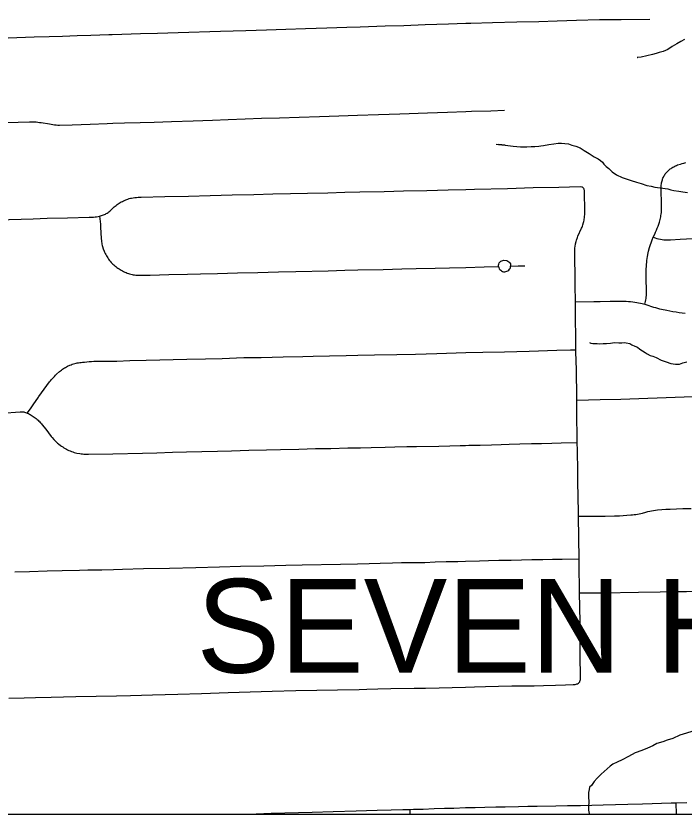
# Model space of a CAD drawing. Extents: x -59 to 82, y -3 to 49.
# Drawn here: x -13.455 to -12.781, y 28.548 to 29.355 of the extents above; entities that cross this region are included whole.
import ezdxf

# ---------------------------------------------------------------- set-up
doc = ezdxf.new("R2010")
doc.units = 0
for name, color, linetype in [('GM_X_City_Street', 7, 'Continuous'), ('GM_X_Corporation', 7, 'Continuous'), ('GM_X_Corporation_Text', 7, 'Continuous'), ('GM_X_County_Road', 7, 'Continuous'), ('GM_X_Minor_River', 7, 'Continuous'), ('SH_Data', 7, 'Continuous')]:
    doc.layers.add(name, color=color, linetype=linetype)

msp = doc.modelspace()

# ---------------------------------------------------------------- linework, layer by layer
at = {"layer": 'GM_X_City_Street'}
for p, q in [((-12.78827, 28.54818), (-12.78831, 28.55954)), ((-13.05725, 28.54818), (-13.05736, 28.55288))]:
    msp.add_line(p, q, dxfattribs=at)
for points in [[(-13.46337, 29.33276), (-13.43718, 29.33366), (-13.42205, 29.33413), (-13.40839, 29.33448), (-13.39371, 29.33497), (-13.37997, 29.33543), (-13.3617, 29.33599), (-13.3582, 29.33609), (-13.34859, 29.33639), (-13.3295, 29.33704), (-13.31241, 29.33749), (-13.29147, 29.33808), (-13.24877, 29.33943), (-13.22319, 29.34018), (-13.20232, 29.34083), (-13.18265, 29.34143), (-13.16294, 29.34206), (-13.1413, 29.34275), (-13.12105, 29.34341), (-13.10769, 29.34386), (-13.08234, 29.34487), (-13.0637, 29.3453), (-13.0422, 29.34605), (-13.01855, 29.34677), (-13.001, 29.34743), (-12.99602, 29.34762), (-12.97416, 29.34817), (-12.94934, 29.34878), (-12.92711, 29.34937), (-12.90856, 29.34997), (-12.88922, 29.35043), (-12.86577, 29.35111), (-12.84394, 29.3513), (-12.81496, 29.35171)], [(-13.47479, 29.2468), (-13.45325, 29.24762), (-13.44195, 29.2479), (-13.43686, 29.24779), (-13.43517, 29.24767), (-13.43348, 29.24751), (-13.43179, 29.24731), (-13.43011, 29.24707), (-13.4216, 29.2457), (-13.41991, 29.24539), (-13.41822, 29.24512), (-13.41651, 29.2449), (-13.4148, 29.24472), (-13.41309, 29.24458), (-13.41136, 29.2445), (-13.3986, 29.24485), (-13.38066, 29.24539), (-13.36336, 29.24601), (-13.35762, 29.24633), (-13.34584, 29.24669), (-13.33, 29.2472), (-13.31575, 29.24755), (-13.29843, 29.24815), (-13.27656, 29.24897), (-13.25699, 29.24964), (-13.24095, 29.25011), (-13.22386, 29.25078), (-13.20728, 29.25138), (-13.18928, 29.25182), (-13.16932, 29.25261), (-13.14871, 29.25321), (-13.12932, 29.25387), (-13.11049, 29.25444), (-13.0891, 29.25519), (-13.0678, 29.25592), (-13.0398, 29.25691), (-13.01944, 29.25761), (-13.00103, 29.2583), (-12.99533, 29.25852), (-12.97585, 29.25911), (-12.96186, 29.2596)], [(-12.81999, 29.06337), (-12.81964, 29.06483), (-12.81933, 29.06631), (-12.81907, 29.06779), (-12.81885, 29.06927), (-12.81868, 29.07077), (-12.81857, 29.07227), (-12.81849, 29.07376), (-12.81878, 29.09285), (-12.81868, 29.0994), (-12.81857, 29.10158), (-12.8184, 29.10376), (-12.8182, 29.10593), (-12.81798, 29.10781), (-12.81772, 29.1097), (-12.81742, 29.11158), (-12.81671, 29.11531), (-12.8163, 29.11717), (-12.81537, 29.12085), (-12.81484, 29.12268), (-12.81341, 29.12662), (-12.81264, 29.12858), (-12.81159, 29.13112), (-12.81015, 29.13435), (-12.80925, 29.13625), (-12.80839, 29.13822), (-12.80757, 29.14021), (-12.80678, 29.14221), (-12.80604, 29.14423), (-12.80535, 29.14626), (-12.80496, 29.14764), (-12.8046, 29.14902), (-12.80429, 29.15042), (-12.80401, 29.15183), (-12.80377, 29.15324), (-12.80358, 29.15466), (-12.80342, 29.15608), (-12.8033, 29.15751), (-12.80323, 29.15894), (-12.80335, 29.17038), (-12.80347, 29.17372), (-12.80362, 29.17705), (-12.8037, 29.17819), (-12.80364, 29.18275), (-12.80352, 29.18388), (-12.80337, 29.185), (-12.80317, 29.18613), (-12.80294, 29.18724), (-12.80266, 29.18835), (-12.80241, 29.18925), (-12.80211, 29.19015), (-12.80177, 29.19103), (-12.80139, 29.19189), (-12.80097, 29.19273), (-12.80051, 29.19356), (-12.80002, 29.19436), (-12.79948, 29.19514), (-12.79892, 29.19588), (-12.79831, 29.19661), (-12.79767, 29.1973), (-12.79692, 29.19806), (-12.79614, 29.1988), (-12.79533, 29.19949), (-12.79449, 29.20016), (-12.79363, 29.20079), (-12.79274, 29.20139), (-12.79183, 29.20195), (-12.7909, 29.20248), (-12.78994, 29.20296), (-12.78898, 29.20342), (-12.78799, 29.20383), (-12.78699, 29.2042), (-12.7842, 29.20513), (-12.78241, 29.20569), (-12.78061, 29.2062), (-12.7788, 29.20668)], [(-13.47484, 29.14867), (-13.43808, 29.14988), (-13.4241, 29.15033), (-13.40347, 29.15088), (-13.38163, 29.15139), (-13.37702, 29.15157), (-13.37547, 29.15168), (-13.37397, 29.15186), (-13.37243, 29.15209), (-13.37121, 29.15235), (-13.36991, 29.15268), (-13.36892, 29.15299), (-13.36794, 29.15334), (-13.36697, 29.15373), (-13.36603, 29.15416), (-13.3651, 29.15462), (-13.36419, 29.15513), (-13.3633, 29.15567), (-13.36244, 29.15624), (-13.3616, 29.15685), (-13.36078, 29.1575), (-13.35918, 29.159), (-13.35711, 29.16099), (-13.35619, 29.16182), (-13.35525, 29.16263), (-13.35429, 29.16341), (-13.35329, 29.16415), (-13.35228, 29.16488), (-13.35124, 29.16556), (-13.35018, 29.16621), (-13.3491, 29.16683), (-13.348, 29.16741), (-13.34689, 29.16796), (-13.34576, 29.16847), (-13.34462, 29.16896), (-13.34346, 29.1694), (-13.34228, 29.1698), (-13.34109, 29.17018), (-13.3399, 29.17051), (-13.33869, 29.1708), (-13.33706, 29.17108), (-13.33541, 29.17131), (-13.33377, 29.17149), (-13.33212, 29.17164), (-13.33046, 29.17175), (-13.32881, 29.17182), (-13.30501, 29.17227), (-13.28101, 29.17279), (-13.25938, 29.17341), (-13.23708, 29.17391), (-13.21507, 29.17447), (-13.19597, 29.17494), (-13.17815, 29.17538), (-13.16084, 29.17582), (-13.14031, 29.17618), (-13.12304, 29.17659), (-13.10809, 29.17698), (-13.08351, 29.17756), (-13.06378, 29.17805), (-13.04026, 29.17857), (-13.01888, 29.17909), (-13.00106, 29.17945), (-12.99228, 29.17963), (-12.95873, 29.18054), (-12.93303, 29.18138), (-12.90692, 29.18188), (-12.88549, 29.18243), (-12.8839, 29.18222), (-12.88352, 29.18207), (-12.88317, 29.18189), (-12.88277, 29.1816), (-12.88231, 29.18114), (-12.88176, 29.18048)], [(-12.88525, 28.68413), (-12.88542, 28.71065), (-12.88555, 28.74249), (-12.88601, 28.77166), (-12.88618, 28.78226), (-12.88636, 28.79084), (-12.88651, 28.80019), (-12.88659, 28.80601), (-12.88671, 28.8275), (-12.88697, 28.84914), (-12.88707, 28.85287), (-12.88773, 28.88413), (-12.88789, 28.89468), (-12.88825, 28.91566), (-12.88833, 28.92362), (-12.88877, 28.95595), (-12.88877, 28.9665), (-12.88885, 28.97722), (-12.88911, 28.98909), (-12.88923, 28.99934), (-12.8894, 29.00421), (-12.88972, 29.0175), (-12.88992, 29.02548), (-12.89007, 29.05393), (-12.89009, 29.06598), (-12.89056, 29.08272), (-12.89065, 29.08966), (-12.89092, 29.11234), (-12.89069, 29.1204), (-12.89052, 29.12173), (-12.89006, 29.12439), (-12.88945, 29.12701), (-12.88909, 29.1283), (-12.88826, 29.13086), (-12.88779, 29.13212), (-12.88403, 29.14023), (-12.88355, 29.14135), (-12.88312, 29.14249), (-12.88272, 29.14364), (-12.88203, 29.14599), (-12.88175, 29.14717), (-12.8815, 29.14837), (-12.8813, 29.14957), (-12.88113, 29.15078), (-12.88101, 29.15199), (-12.88088, 29.15433), (-12.8808, 29.15667), (-12.88122, 29.17818), (-12.88143, 29.17984), (-12.88176, 29.18048)], [(-13.37121, 29.15235), (-13.37083, 29.14965), (-13.3705, 29.14694), (-13.37021, 29.14423), (-13.36996, 29.14151), (-13.36936, 29.12988), (-13.3692, 29.12755), (-13.36906, 29.12639), (-13.36888, 29.12524), (-13.36866, 29.12409), (-13.3684, 29.12296), (-13.36811, 29.12183), (-13.36741, 29.11961), (-13.36651, 29.11727), (-13.36597, 29.11604), (-13.3654, 29.11483), (-13.36479, 29.11364), (-13.36413, 29.11247), (-13.36344, 29.11132), (-13.36271, 29.1102), (-13.36195, 29.1091), (-13.36114, 29.10803), (-13.3603, 29.10698), (-13.35923, 29.10581), (-13.3577, 29.10411), (-13.35671, 29.1032), (-13.35569, 29.10232), (-13.35465, 29.10148), (-13.35358, 29.10066), (-13.35248, 29.09989), (-13.35137, 29.09914), (-13.35023, 29.09843), (-13.34907, 29.09775), (-13.34789, 29.09711), (-13.34669, 29.0965), (-13.34547, 29.09593), (-13.34424, 29.09539), (-13.34306, 29.09496), (-13.34187, 29.09455), (-13.34067, 29.09419), (-13.33945, 29.09387), (-13.33822, 29.09359), (-13.33699, 29.09334), (-13.33575, 29.09313), (-13.3345, 29.09297), (-13.33325, 29.09284), (-13.332, 29.09276), (-13.31984, 29.09295), (-13.30107, 29.09345), (-13.28226, 29.09393), (-13.2691, 29.09418), (-13.25195, 29.09462), (-13.23169, 29.09506), (-13.21127, 29.09565), (-13.19028, 29.09618), (-13.17267, 29.09659), (-13.13993, 29.09738), (-13.12329, 29.09776), (-13.1101, 29.09812), (-13.08461, 29.09866), (-13.0656, 29.09915), (-13.05098, 29.09943), (-13.03206, 29.09986), (-13.01744, 29.10024), (-13.00108, 29.10074), (-12.98234, 29.1013), (-12.96801, 29.10171)], [(-12.81159, 29.13112), (-12.80982, 29.13058), (-12.80803, 29.13007), (-12.80624, 29.12962), (-12.80444, 29.12921), (-12.80266, 29.12877), (-12.80079, 29.12854), (-12.79799, 29.12847), (-12.79426, 29.12857), (-12.78424, 29.12919), (-12.77156, 29.12999)], [(-12.96801, 29.10171), (-12.96788, 29.10304), (-12.96768, 29.10411), (-12.96728, 29.10517), (-12.96631, 29.1062), (-12.96548, 29.10683), (-12.96456, 29.10733), (-12.96359, 29.10769), (-12.96256, 29.1079), (-12.95947, 29.10762), (-12.95838, 29.10706), (-12.9574, 29.10632), (-12.95654, 29.10545), (-12.95594, 29.1043), (-12.95574, 29.10324), (-12.95567, 29.10205)], [(-12.96801, 29.10171), (-12.96775, 29.10045), (-12.96722, 29.09926), (-12.96655, 29.09853), (-12.96567, 29.09774), (-12.96489, 29.09713), (-12.96401, 29.09667), (-12.96306, 29.09638), (-12.96171, 29.09627), (-12.96048, 29.09645), (-12.95943, 29.0968), (-12.95844, 29.09731), (-12.95755, 29.09797), (-12.95678, 29.09876), (-12.95607, 29.09972), (-12.9558, 29.10059), (-12.95567, 29.10205)], [(-12.95567, 29.10205), (-12.94803, 29.10215), (-12.94127, 29.10225)], [(-12.89009, 29.06598), (-12.87171, 29.06611), (-12.8651, 29.06632), (-12.85529, 29.06643), (-12.84326, 29.06661), (-12.83885, 29.06647), (-12.83665, 29.06633), (-12.83445, 29.06614), (-12.83225, 29.0659), (-12.83007, 29.06562), (-12.8282, 29.06529), (-12.82634, 29.06493), (-12.8245, 29.06454), (-12.82266, 29.0641), (-12.81999, 29.06337), (-12.81721, 29.06253), (-12.81341, 29.06125), (-12.81139, 29.06062), (-12.80936, 29.06002), (-12.80731, 29.05947), (-12.80526, 29.05895), (-12.80319, 29.05847), (-12.798, 29.05738), (-12.79487, 29.05676), (-12.79175, 29.05617), (-12.78861, 29.05563), (-12.78546, 29.05513), (-12.78231, 29.05467), (-12.77947, 29.05437)], [(-13.46983, 28.95344), (-13.45122, 28.95486), (-13.44849, 28.9547), (-13.44763, 28.95457), (-13.44678, 28.95439), (-13.44594, 28.95417), (-13.44401, 28.95351), (-13.44089, 28.95771), (-13.43806, 28.96185), (-13.43275, 28.9696), (-13.43229, 28.97015), (-13.42152, 28.98487), (-13.42062, 28.98606), (-13.41968, 28.98723), (-13.4177, 28.98949), (-13.41667, 28.99059), (-13.41561, 28.99165), (-13.41452, 28.99268), (-13.41146, 28.99538), (-13.41053, 28.99619), (-13.40956, 28.99696), (-13.40857, 28.99769), (-13.40756, 28.99839), (-13.40652, 28.99906), (-13.40546, 28.99968), (-13.40438, 29.00027), (-13.40327, 29.00082), (-13.40101, 29.00184), (-13.39979, 29.00233), (-13.39857, 29.00277), (-13.39733, 29.00318), (-13.39608, 29.00354), (-13.39481, 29.00385), (-13.39354, 29.00413), (-13.39225, 29.00436), (-13.39097, 29.00455), (-13.38967, 29.0047), (-13.38841, 29.00479), (-13.38607, 29.00507), (-13.38373, 29.00531), (-13.38139, 29.00552), (-13.37904, 29.00568), (-13.37669, 29.0058), (-13.35358, 29.00605), (-13.34053, 29.00644), (-13.32398, 29.00685), (-13.2827, 29.00782), (-13.26396, 29.00841), (-13.24722, 29.00876), (-13.22513, 29.00948), (-13.20758, 29.00976), (-13.18542, 29.01022), (-13.16559, 29.01056), (-13.15514, 29.01086), (-13.13869, 29.0112), (-13.12185, 29.01168), (-13.11021, 29.01204), (-13.09313, 29.01231), (-13.07052, 29.01263), (-13.0518, 29.01292), (-13.03036, 29.01378), (-13.00111, 29.01455), (-12.98382, 29.01501), (-12.96185, 29.01532), (-12.93685, 29.01617), (-12.90917, 29.01693), (-12.89523, 29.01734), (-12.88972, 29.0175)], [(-12.88877, 28.9665), (-12.86507, 28.96702), (-12.84433, 28.96756), (-12.78033, 28.96995), (-12.76452, 28.97049), (-12.74679, 28.97101), (-12.71544, 28.97209), (-12.70069, 28.97276), (-12.6945, 28.97269), (-12.6932, 28.97255), (-12.69191, 28.97237), (-12.69063, 28.97214), (-12.68935, 28.97188), (-12.68808, 28.97157), (-12.68682, 28.97123), (-12.68557, 28.97084), (-12.68434, 28.97041), (-12.68311, 28.96995), (-12.68191, 28.96944)], [(-13.44401, 28.95351), (-13.44269, 28.95291), (-13.44193, 28.9525), (-13.44118, 28.95206), (-13.4401, 28.95146), (-13.43903, 28.95082), (-13.438, 28.95014), (-13.43698, 28.94943), (-13.43599, 28.94869), (-13.43503, 28.94792), (-13.43409, 28.9471), (-13.43317, 28.94626), (-13.43229, 28.94539), (-13.43144, 28.94449), (-13.43062, 28.94357), (-13.42983, 28.94261), (-13.42908, 28.94163), (-13.42541, 28.93704), (-13.41977, 28.92961), (-13.41895, 28.92861), (-13.41724, 28.92667), (-13.41634, 28.92573), (-13.41445, 28.92395), (-13.41348, 28.92309), (-13.41248, 28.92227), (-13.41041, 28.92071), (-13.40934, 28.91997), (-13.40823, 28.91925), (-13.40702, 28.91847), (-13.4058, 28.91774), (-13.40457, 28.91705), (-13.40331, 28.9164), (-13.40203, 28.91578), (-13.40073, 28.9152), (-13.39942, 28.91467), (-13.3981, 28.91418), (-13.3968, 28.91374), (-13.394, 28.91308), (-13.39111, 28.91256), (-13.38966, 28.91236), (-13.38821, 28.91219), (-13.38675, 28.91208), (-13.3822, 28.91187), (-13.35744, 28.91227), (-13.32769, 28.91297), (-13.31319, 28.91331), (-13.29728, 28.91379), (-13.28308, 28.91418), (-13.26782, 28.91451), (-13.2517, 28.91501), (-13.23776, 28.91529), (-13.2202, 28.91581), (-13.20221, 28.91625), (-13.18807, 28.91661), (-13.16958, 28.91707), (-13.15271, 28.91754), (-13.13719, 28.91773), (-13.12031, 28.91817), (-13.10747, 28.91829), (-13.09658, 28.91853), (-13.08232, 28.91907), (-13.07271, 28.91923), (-13.06056, 28.91955), (-13.05078, 28.91966), (-13.02832, 28.91996), (-13.01707, 28.92042), (-13.00672, 28.92065), (-13.00114, 28.92081), (-12.99795, 28.9209), (-12.98639, 28.92116), (-12.97497, 28.92152), (-12.9652, 28.92179), (-12.95706, 28.92198), (-12.94629, 28.92232), (-12.93467, 28.92258), (-12.92463, 28.92286), (-12.91401, 28.92309), (-12.9047, 28.92327), (-12.88833, 28.92362)], [(-12.88697, 28.84914), (-12.86015, 28.8494), (-12.85091, 28.8496), (-12.84562, 28.84972), (-12.84187, 28.84991), (-12.83813, 28.85015), (-12.83438, 28.85044), (-12.83268, 28.85059), (-12.83099, 28.85079), (-12.8293, 28.85103), (-12.82761, 28.85132), (-12.82593, 28.85164), (-12.82426, 28.85201), (-12.82259, 28.85242), (-12.81904, 28.85336), (-12.81711, 28.85382), (-12.81516, 28.85423), (-12.81321, 28.85461), (-12.81125, 28.85495), (-12.80927, 28.85524), (-12.80718, 28.85553), (-12.80298, 28.85599), (-12.79877, 28.85631), (-12.79455, 28.85648), (-12.78157, 28.85698), (-12.77337, 28.85687)], [(-13.45649, 28.7931), (-13.44187, 28.79342), (-13.42384, 28.79385), (-13.40867, 28.79423), (-13.39134, 28.79466), (-13.38278, 28.79494), (-13.36858, 28.79517), (-13.35682, 28.79545), (-13.34784, 28.79571), (-13.32648, 28.79625), (-13.30021, 28.79679), (-13.27371, 28.7974), (-13.24997, 28.79797), (-13.2286, 28.79855), (-13.20504, 28.79896), (-13.18292, 28.79958), (-13.1663, 28.7999), (-13.12749, 28.80077), (-13.11041, 28.80117), (-13.09858, 28.80149), (-13.08738, 28.80173), (-13.07517, 28.80201), (-13.06588, 28.80227), (-13.05595, 28.80244), (-13.04236, 28.80259), (-13.0318, 28.80293), (-13.02087, 28.80333), (-13.00909, 28.80359), (-13.00117, 28.80381), (-12.98722, 28.80419), (-12.97792, 28.80445), (-12.96767, 28.80468), (-12.95504, 28.80485), (-12.94479, 28.80508), (-12.93428, 28.80537), (-12.92324, 28.80557), (-12.91352, 28.80573), (-12.90369, 28.80587), (-12.88659, 28.80601)], [(-12.88601, 28.77166), (-12.87128, 28.77183), (-12.86319, 28.77191), (-12.82635, 28.77242), (-12.80447, 28.77263), (-12.78844, 28.77297), (-12.77806, 28.77311), (-12.76694, 28.77329), (-12.76628, 28.77341), (-12.76562, 28.77357), (-12.76497, 28.77377), (-12.76433, 28.774), (-12.76372, 28.77428), (-12.76311, 28.77459), (-12.76253, 28.77493), (-12.76197, 28.77531), (-12.76143, 28.77573), (-12.76092, 28.77617), (-12.76044, 28.77664), (-12.75998, 28.77715), (-12.75955, 28.77767), (-12.75913, 28.77839), (-12.75873, 28.77912), (-12.75817, 28.78032)], [(-13.46253, 28.66513), (-13.44712, 28.66556), (-13.43586, 28.66591), (-13.41993, 28.66618), (-13.39502, 28.66684), (-13.35381, 28.66763), (-13.33964, 28.66799), (-13.31736, 28.66869), (-13.29201, 28.66939), (-13.26796, 28.67012), (-13.24102, 28.67093), (-13.21898, 28.67163), (-13.19648, 28.6723), (-13.17255, 28.67302), (-13.15141, 28.67351), (-13.13075, 28.67382), (-13.10863, 28.6741), (-13.10106, 28.67434), (-13.08991, 28.67465), (-13.07681, 28.67504), (-13.05303, 28.67531), (-13.04167, 28.67546), (-13.02783, 28.67577), (-13.01468, 28.67612), (-13.00122, 28.67647), (-12.99217, 28.67662), (-12.98103, 28.67698), (-12.96782, 28.67727), (-12.95445, 28.67762), (-12.94399, 28.6777), (-12.93183, 28.67791), (-12.92254, 28.67817), (-12.91045, 28.6785), (-12.90035, 28.67873), (-12.89238, 28.67895), (-12.8906, 28.67912), (-12.8896, 28.67932), (-12.88864, 28.67963), (-12.88805, 28.67992), (-12.88716, 28.68047), (-12.88684, 28.6807), (-12.88639, 28.68111), (-12.88611, 28.68146), (-12.8859, 28.6818), (-12.88562, 28.6824), (-12.88539, 28.68316), (-12.88525, 28.68413)]]:
    msp.add_lwpolyline(points, dxfattribs=at)
at = {"layer": 'GM_X_Corporation'}
msp.add_lwpolyline([(-13.52299, 28.54818), (-12.26933, 28.54818), (-12.27027, 28.59659), (-12.2729, 28.785), (-12.27445, 28.85071), (-12.27791, 28.91868), (-12.28038, 28.99768), (-12.28322, 29.16948), (-12.39731, 29.16675), (-12.40536, 29.65746), (-12.4237, 30.70496), (-12.43226, 31.1727), (-12.72864, 31.16365), (-12.73395, 31.43938), (-13.02009, 31.4299), (-13.03296, 31.63451), (-13.58864, 31.61196), (-13.56634, 31.07809), (-13.54667, 29.93943), (-13.53977, 29.62717)], close=True, dxfattribs=at)
at = {"layer": 'GM_X_County_Road'}
msp.add_lwpolyline([(-13.22018, 28.54818), (-13.19759, 28.54894), (-13.15612, 28.5501), (-13.13504, 28.55068), (-13.11176, 28.55146), (-13.10146, 28.55175), (-13.09053, 28.55215), (-13.07643, 28.55247), (-13.06465, 28.55268), (-13.05736, 28.55288), (-13.05382, 28.55297), (-13.04415, 28.55324), (-13.03306, 28.55365), (-13.0226, 28.55399), (-13.01314, 28.5542), (-13.00125, 28.55465), (-12.99159, 28.55494), (-12.98187, 28.55516), (-12.97054, 28.5554), (-12.96106, 28.55552), (-12.94769, 28.55583), (-12.93839, 28.55608), (-12.92899, 28.55629), (-12.91015, 28.55652), (-12.89813, 28.55677), (-12.88498, 28.55696), (-12.86204, 28.55753), (-12.83727, 28.55804), (-12.8223, 28.55852), (-12.79339, 28.55939), (-12.78831, 28.55954), (-12.77777, 28.55985)], dxfattribs=at)
at = {"layer": 'GM_X_Minor_River'}
for points in [[(-12.78, 29.33105), (-12.78377, 29.3291), (-12.78791, 29.32677), (-12.79243, 29.32406), (-12.79695, 29.32096), (-12.80148, 29.31901), (-12.80564, 29.31782), (-12.80866, 29.31702), (-12.81244, 29.31584), (-12.8238, 29.31304), (-12.82721, 29.313), (-12.82797, 29.31299), (-12.82759, 29.31299)], [(-12.97028, 29.22538), (-12.96116, 29.22435), (-12.968, 29.22503), (-12.96116, 29.22435), (-12.95317, 29.22331), (-12.94557, 29.22264), (-12.93949, 29.22271), (-12.93494, 29.22277), (-12.93114, 29.22281), (-12.92735, 29.22324), (-12.92508, 29.22365), (-12.92243, 29.22406), (-12.91712, 29.22488), (-12.9122, 29.2257), (-12.90765, 29.22614), (-12.90423, 29.22618), (-12.90081, 29.22584), (-12.89739, 29.2255), (-12.89396, 29.2244), (-12.88977, 29.22331), (-12.88557, 29.22146), (-12.88135, 29.21886), (-12.87638, 29.21588), (-12.8714, 29.21252), (-12.86719, 29.21029), (-12.86489, 29.2088), (-12.86297, 29.20692), (-12.86142, 29.20504), (-12.85911, 29.20278), (-12.85642, 29.20054), (-12.85296, 29.19716), (-12.84874, 29.19417), (-12.84301, 29.19158), (-12.83805, 29.18974), (-12.83386, 29.18865), (-12.82852, 29.18681), (-12.82395, 29.18535), (-12.81823, 29.18352), (-12.81366, 29.18281), (-12.80985, 29.18172), (-12.80186, 29.18067), (-12.79958, 29.18032), (-12.79692, 29.17997), (-12.79387, 29.17925), (-12.79082, 29.17853), (-12.78588, 29.17783), (-12.78169, 29.17712), (-12.77712, 29.17642)], [(-12.87593, 29.02475), (-12.87451, 29.02399), (-12.87261, 29.02363), (-12.86843, 29.02368), (-12.86577, 29.02333), (-12.86236, 29.02375), (-12.85894, 29.02379), (-12.85477, 29.02422), (-12.8506, 29.02465), (-12.84642, 29.02433), (-12.84338, 29.02436), (-12.84111, 29.02477), (-12.83883, 29.02442), (-12.8354, 29.0237), (-12.83311, 29.02259), (-12.83005, 29.0211), (-12.82738, 29.01999), (-12.82507, 29.01812), (-12.82239, 29.01625), (-12.81971, 29.01477), (-12.81779, 29.01327), (-12.81473, 29.01179), (-12.81207, 29.01106), (-12.80863, 29.00958), (-12.80366, 29.00698), (-12.7987, 29.00514), (-12.79374, 29.00368), (-12.78918, 29.00298), (-12.785, 29.00303), (-12.7816, 29.00421), (-12.77782, 29.00539)], [(-12.75912, 28.63573), (-12.78473, 28.62783), (-12.79186, 28.6246), (-12.79751, 28.62293), (-12.80202, 28.62129), (-12.80805, 28.61961), (-12.81217, 28.61722), (-12.81742, 28.6148), (-12.82305, 28.61237), (-12.82982, 28.60991), (-12.83656, 28.60631), (-12.84293, 28.6031), (-12.84818, 28.60068), (-12.8523, 28.59867), (-12.85529, 28.59669), (-12.85826, 28.59395), (-12.86418, 28.58847), (-12.86826, 28.58456), (-12.8712, 28.58106), (-12.87413, 28.57718), (-12.87598, 28.57523), (-12.8763, 28.57294), (-12.87698, 28.56988), (-12.87686, 28.5657)], [(-12.87686, 28.5657), (-12.87672, 28.56038), (-12.87697, 28.55543), (-12.87687, 28.55201), (-12.8764, 28.5486), (-12.87623, 28.54818)]]:
    msp.add_lwpolyline(points, dxfattribs=at)
at = {"layer": 'SH_Data'}
msp.add_lwpolyline([(-15.07858, 28.54818), (-8.27858, 28.54818), (-8.27858, 35.34818), (-15.07858, 35.34818)], close=True, dxfattribs=at)

# ---------------------------------------------------------------- texts
at = {"layer": 'GM_X_Corporation_Text'}
msp.add_text('SEVEN HILLS', height=0.094697, rotation=0.00001, dxfattribs=at).set_placement((-13.27309, 28.69106))

doc.saveas('drawing.dxf')
